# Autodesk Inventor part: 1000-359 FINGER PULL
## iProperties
Created: 2007-03
Part Number: 1000-359 FINGER PULL
Document SubType Name: Modeling
Designer: Andy Moles
Material: Steel
Mass: 23.5124 g
Surface Area: 35.2252 cm^2
Volume: 2.99522 cm^3
Density: 7.85 g/cm^3
Translation Standard: STEP AP203
File Name: 1000-359_PRT
Preprocessor: PRO/ENGINEER BY PARAMETRIC TECHNOLOGY CORPORATION, 2001390
Postprocessor: Build: 344b, Release: 11 SP2 - Date: Fri 08/18/2006
Sent Units: MILLIMETERS
Uncertainty: 0.007209068323802
Author: Andy Moles
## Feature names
1. Base1
